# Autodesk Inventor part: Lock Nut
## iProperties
Created: 2002-02
Part Number: Lock Nut
Document SubType Name: Modeling
Designer: ***
Control State: 0
Master: False
Checked Out: False
Shininess: 77.0
Length Units: 11269
Angle Units: 11279
Time Units: 11290
Mass Units: 11283
Length Display Precision: 3
Angle Display Precision: 2
Density: 0.0
Volumn: 0.0
Area: 0.0
PropertySet Name: Model Information
Author: ***
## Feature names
1. Extrusion1
2. Fillet1
3. Extrusion2
4. Hole1
